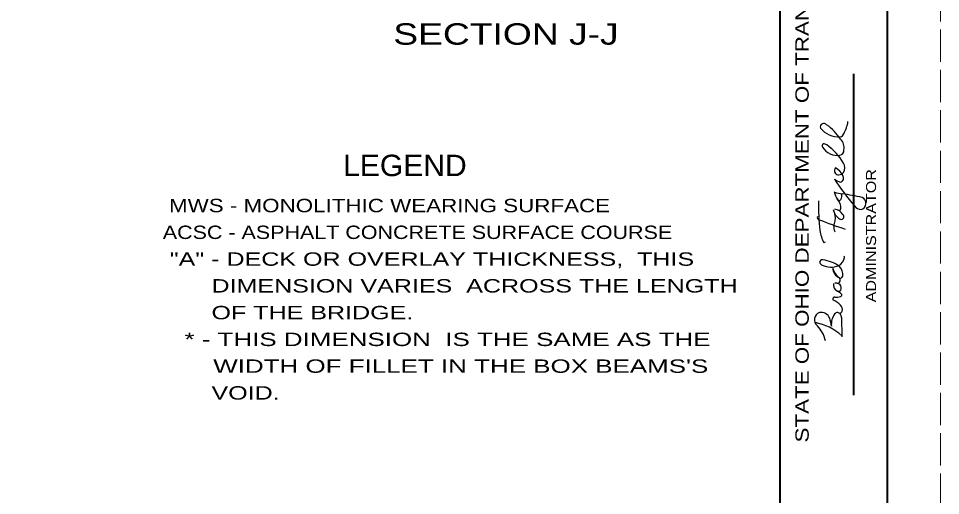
# Model space of a CAD drawing. Extents: x 1285 to 1427, y 1365 to 1427.
# Drawn here: x 1415.18 to 1426.67, y 1411.82 to 1417.76 of the extents above; entities that cross this region are included whole.
import ezdxf
from ezdxf.enums import TextEntityAlignment as Align

# ---------------------------------------------------------------- set-up
doc = ezdxf.new("R2010")
doc.units = 0
doc.header["$LTSCALE"] = 0.067
doc.linetypes.add('LONG_DASHED', pattern=[7.5, 6, -1.5])
for name, color, linetype, lineweight in [('1', 7, 'Continuous', 40), ('43', 7, 'Continuous', 25), ('44', 7, 'Continuous', 13)]:
    doc.layers.add(name, color=color, linetype=linetype, lineweight=lineweight)

msp = doc.modelspace()

# ---------------------------------------------------------------- linework, layer by layer
at = {"layer": '1'}
for p, q in [((1424.66667, 1398), (1424.66667, 1426)), ((1425.58544, 1413.06933), (1425.58544, 1417.06933))]:
    msp.add_line(p, q, dxfattribs=at)
at = {"layer": '1', "linetype": 'LONG_DASHED', "lineweight": 13}
msp.add_lwpolyline([(1381.33333, 1426.66667), (1426.66667, 1426.66667), (1426.66667, 1397.33333), (1381.33333, 1397.33333)], close=True, dxfattribs=at)
at = {"layer": '1'}
msp.add_lwpolyline([(1384, 1426), (1426, 1426), (1426, 1398), (1384, 1398)], close=True, dxfattribs=at)
at = {"layer": '43'}
for p, q in [((1425.58544, 1413.06933), (1425.58544, 1417.06933)), ((1425.34789, 1415.10722), (1425.35878, 1415.111)), ((1425.43356, 1414.03556), (1425.43789, 1413.79789))]:
    msp.add_line(p, q, dxfattribs=at)
for centre, radius, start, end in [((1425.21212, 1416.40995), 0.0444, 113.98019, 198.40352), ((1425.20855, 1416.39627), 0.05616, 45.85596, 104.94474), ((1424.8206, 1415.84326), 0.73103, 34.63262, 54.25344), ((1425.12137, 1416.52764), 0.39479, 329.12441, 352.69329), ((1425.40091, 1416.57947), 0.29498, 218.47768, 273.26047), ((1425.39668, 1416.34987), 0.06821, 287.93982, 338.66307), ((1425.22172, 1416.17314), 0.02998, 124.49102, 212.28704), ((1425.21397, 1416.14582), 0.05284, 48.28094, 100.06036), ((1424.86837, 1415.62818), 0.67478, 29.47671, 55.64687), ((1425.30517, 1416.14954), 0.15997, 350.92499, 43.03504), ((1425.38173, 1416.27434), 0.21931, 212.30855, 277.889), ((1425.40249, 1416.11742), 0.06104, 278.80614, 6.47651), ((1425.36388, 1415.89986), 0.10996, 328.86402, 33.28654), ((1425.39522, 1415.86332), 0.05046, 134.5839, 276.21021), ((1425.25127, 1415.71199), 0.21645, 24.97701, 59.9081), ((1425.39771, 1415.88883), 0.07573, 272.24638, 322.76314), ((1428.38224, 1417.77289), 3.64497, 213.54695, 220.08659), ((1425.50594, 1416.00132), 0.29155, 236.35413, 252.38173), ((1425.4102, 1415.77175), 0.04888, 278.82355, 40.31415), ((1425.5934, 1415.65823), 0.2578, 191.93662, 216.93201), ((1425.54779, 1416.28376), 0.71555, 253.73211, 261.66584), ((1425.26411, 1415.39941), 0.16158, 356.67266, 44.91278), ((1425.40462, 1415.51462), 0.02065, 213.1438, 334.3378), ((1425.37611, 1415.5457), 0.06182, 319.65709, 31.03704), ((1425.08284, 1412.93154), 2.66879, 76.85896, 82.22082), ((1425.65938, 1415.45831), 0.0782, 282.55689, 67.28157), ((1427.98842, 1415.43924), 2.84328, 179.00808, 186.45308), ((1425.49387, 1415.40728), 0.16551, 190.08126, 239.27146), ((1424.98629, 1415.21951), 0.37945, 13.60485, 24.73867), ((1425.3284, 1415.24507), 0.14238, 31.60989, 82.17754), ((1425.3993, 1415.39972), 0.02786, 240.6235, 339.64142), ((1425.68427, 1415.49713), 0.11542, 218.20712, 266.08129), ((1425.15742, 1415.28181), 0.02714, 153.49478, 263.55592), ((1425.00792, 1415.28532), 0.34797, 341.67711, 3.86341), ((1425.42948, 1415.29235), 0.03398, 233.58324, 53.58324), ((1426.68362, 1418.98416), 4.03068, 247.70329, 252.57637), ((1425.46429, 1415.15835), 0.12726, 172.05872, 203.71441), ((1425.7996, 1415.23329), 0.64651, 190.12054, 204.37157), ((1425.15656, 1415.0668), 0.11397, 298.36136, 311.08751), ((1425.19088, 1414.72637), 0.02997, 69.75906, 198.23256), ((1425.21181, 1414.7379), 0.05365, 202.93968, 246.57643), ((1425.12893, 1414.26939), 0.49046, 55.75095, 81.52104), ((1425.32029, 1414.8144), 0.15234, 301.08449, 348.26264), ((1425.44611, 1414.78809), 0.0238, 348.64966, 27.37763), ((1425.46203, 1414.6567), 0.13848, 181.88257, 246.32734), ((1425.53177, 1414.70392), 0.21449, 193.96867, 234.24124), ((1425.31242, 1414.57362), 0.13712, 349.99119, 47.55407), ((1425.41096, 1414.44119), 0.08067, 166.84439, 250.80516), ((1425.36172, 1414.39317), 0.07279, 59.10443, 99.26983), ((1425.37917, 1414.50252), 0.03861, 269.53454, 45.09708), ((1425.41888, 1414.55642), 0.02933, 244.8672, 346.93776), ((1425.39531, 1414.39735), 0.03419, 245.21977, 351.61479), ((1424.8706, 1413.60569), 0.91683, 52.41014, 55.91351), ((1425.37479, 1414.40533), 0.05587, 346.57725, 64.21305), ((1425.35205, 1414.26445), 0.02767, 98.82115, 193.06115), ((1425.19175, 1413.98036), 0.30817, 42.72148, 64.36086), ((1425.36796, 1414.47079), 0.18012, 263.57652, 288.13161), ((1425.42027, 1414.3171), 0.01789, 282.06688, 57.53058), ((1425.4038, 1414.12692), 0.03935, 278.12859, 343.88559), ((1425.36871, 1414.13319), 0.07489, 346.73401, 48.68598), ((1425.19083, 1414.00844), 0.09523, 110.48712, 231.46083), ((1425.17933, 1413.98646), 0.11331, 20.71835, 101.10772), ((1424.7228, 1413.85021), 0.58951, 7.54019, 17.40463), ((1425.53016, 1413.95368), 0.22479, 144.2131, 186.6803), ((1425.38, 1414.05578), 0.04357, 27.88325, 137.63831), ((1425.32668, 1414.0191), 0.10811, 8.73681, 31.85217), ((1424.98456, 1413.30711), 0.67606, 47.9273, 79.95075), ((1424.83133, 1413.64937), 0.41363, 13.62785, 43.47233)]:
    msp.add_arc(centre, radius, start, end, dxfattribs=at)
msp.add_ellipse((1425.3057, 1414.93101), major_axis=(-0.11521, -0.24233), ratio=0.970189, start_param=6.28318531, end_param=7.10295967, dxfattribs=at)

# ---------------------------------------------------------------- texts
at = {"layer": '1'}
for s, height, width, p in [('STATE OF OHIO DEPARTMENT OF TRANSPORTATION', 0.1667, 1.25, (1425.02433, 1416.11006)), ('ADMINISTRATOR', 0.125, 1.2, (1425.86311, 1415.05511))]:
    msp.add_text(s, height=height, rotation=90, dxfattribs=dict(at, width=width)).set_placement(p, align=Align.CENTER)
at = {"layer": '44'}
for s, width, p in [('SECTION J-J', 1.3, (1421.25178, 1417.434)), ('LEGEND', 1.05, (1419.99328, 1415.79722))]:
    msp.add_text(s, height=0.2667, dxfattribs=dict(at, width=width)).set_placement(p, align=Align.CENTER)
for s, width, p in [(' MWS - MONOLITHIC WEARING SURFACE', 1.25, (1416.97656, 1415.34767)), ('ACSC - ASPHALT CONCRETE SURFACE COURSE', 1.2, (1416.97656, 1415.01433)), (' "A" - DECK OR OVERLAY THICKNESS,  THIS ', 1.4, (1416.97656, 1414.681)), ('       DIMENSION VARIES  ACROSS THE LENGTH ', 1.4, (1416.97656, 1414.34767)), ('       OF THE BRIDGE.', 1.4, (1416.97656, 1414.01433)), ('   * - THIS DIMENSION  IS THE SAME AS THE', 1.45, (1416.97656, 1413.681)), ("       WIDTH OF FILLET IN THE BOX BEAMS'S", 1.45, (1416.97656, 1413.34767)), ('       VOID.', 1.4, (1416.97656, 1413.01433))]:
    msp.add_text(s, height=0.1667, dxfattribs=dict(at, width=width)).set_placement(p)

doc.saveas('drawing.dxf')
